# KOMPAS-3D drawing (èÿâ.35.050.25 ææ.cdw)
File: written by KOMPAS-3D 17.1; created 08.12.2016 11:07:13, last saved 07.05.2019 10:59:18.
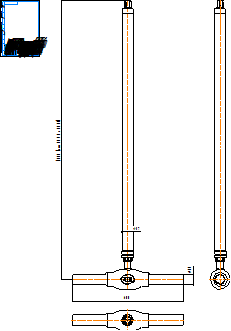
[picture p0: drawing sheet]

Sheet 1: A4, portrait

Title block, sheet 1: name: КШГ.35.050.25 СС; material: Внимание! Данный продукт является объектом авторского права ООО «Торговый Дом АДЛ». / Запрещается изменение, копирование, распространение / (в том числе путем копирования на другие сайты и ресурсы в Интернете) / или любое иное использование информации и объектов без предварительного / согласия правообладателя (ООО «Торговый Дом АДЛ»).; sheets: 1; organisation: ООО "Торговый дом АДЛ"; sheet format: A4; stored path: C:\Users\kka\KOMPAS_Work\Модели кранов для исследований\DN65\С удлинением\КШГ.35.050.25 СС ГЧ _ Шаровой кран БИВАЛ Ду50 Ру2,5 МПа полнопроходной под приварку, c удлинением штока H=950 Габаритный чертеж Lстр600.cdw; drawn by: Климкович К.А.; drawn by, date: 07.12.16

Views: Вид 1, Проекционный вид 2, Проекционный вид 3
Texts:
  Klimkovich
  ADL
  (от 287 до 5000)
Dimensions and other numbers on the sheet: 600; 57; 1500; 1:1; 1; 07.12.16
